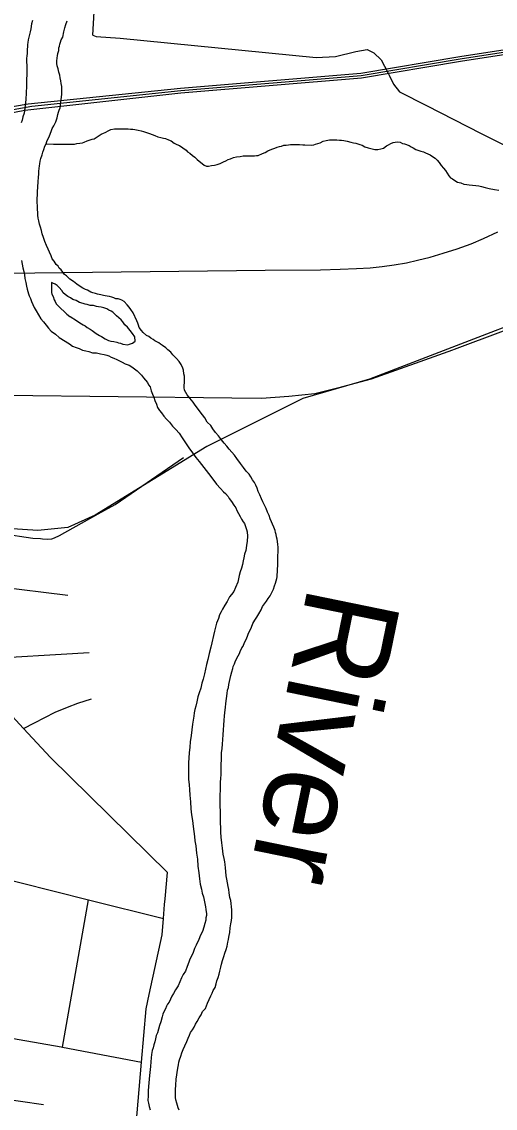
# Model space of a CAD drawing. Extents: x 0 to 44.3, y 0 to 22.
# Drawn here: x 5.125 to 5.6, y 17.715 to 18.805 of the extents above; entities that cross this region are included whole.
import ezdxf

# ---------------------------------------------------------------- set-up
doc = ezdxf.new("R2010")
doc.units = 0
for name, color, linetype in [('GM_X_City_Street', 7, 'Continuous'), ('GM_X_County_Road', 7, 'Continuous'), ('GM_X_Major_River', 7, 'Continuous'), ('GM_X_Major_River_Text', 7, 'Continuous'), ('GM_X_Minor_River', 7, 'Continuous'), ('GM_X_Rail_Line', 7, 'Continuous'), ('GM_X_State_Route', 7, 'Continuous'), ('GM_X_US_Route', 7, 'Continuous')]:
    doc.layers.add(name, color=color, linetype=linetype)

msp = doc.modelspace()

# ---------------------------------------------------------------- linework, layer by layer
at = {"layer": 'GM_X_City_Street'}
for p, q in [((5.0986, 18.2388), (5.1713, 18.2298)), ((5.1659, 17.7763), (5.192, 17.924)), ((5.092, 17.7266), (5.1469, 17.7186))]:
    msp.add_line(p, q, dxfattribs=at)
for points in [[(5.2016, 18.3113), (5.2187, 18.3209), (5.2872, 18.368)], [(5.105, 18.2915), (5.136, 18.287), (5.1437, 18.2866), (5.1459, 18.2864), (5.1504, 18.2859), (5.1551, 18.2863), (5.1578, 18.2873), (5.1628, 18.2896), (5.2016, 18.3113)], [(5.1078, 18.1672), (5.1644, 18.1705), (5.1927, 18.1721)], [(5.1266, 18.0961), (5.1376, 18.1017), (5.1583, 18.1124), (5.1709, 18.1175), (5.1813, 18.1215), (5.1948, 18.1258)], [(4.9677, 17.9802), (5.0685, 17.955), (5.1231, 17.9413), (5.192, 17.924), (5.2672, 17.9052)], [(5.0432, 17.7976), (5.1008, 17.7876), (5.1644, 17.7766), (5.1659, 17.7763), (5.2452, 17.7611)]]:
    msp.add_lwpolyline(points, dxfattribs=at)
at = {"layer": 'GM_X_County_Road'}
msp.add_line((5.5861, 18.6932), (5.7119, 18.6293), dxfattribs=at)
for points in [[(5.1962, 18.7916), (5.2074, 18.9861), (5.21, 19.0351), (5.2114, 19.0611), (5.2076, 19.0746), (5.2007, 19.0831)], [(5.1962, 18.7916), (5.1996, 18.7904), (5.2237, 18.7888), (5.4206, 18.7694), (5.44, 18.7703), (5.4603, 18.7755), (5.4717, 18.7774), (5.4783, 18.7741), (5.4859, 18.767), (5.4925, 18.7542), (5.4938, 18.7515)], [(5.4938, 18.7515), (5.4982, 18.7424), (5.5043, 18.7348), (5.5313, 18.7211), (5.5861, 18.6932)]]:
    msp.add_lwpolyline(points, dxfattribs=at)
at = {"layer": 'GM_X_Major_River'}
for points in [[(5.1358, 18.8064), (5.1347, 18.803), (5.134, 18.7981), (5.1333, 18.795), (5.1315, 18.787), (5.1311, 18.7843), (5.1308, 18.7824), (5.1308, 18.7798), (5.1304, 18.7779), (5.1305, 18.776), (5.1305, 18.7737), (5.1301, 18.7706), (5.1298, 18.7687), (5.1298, 18.7664), (5.1298, 18.7642), (5.1299, 18.7619), (5.1299, 18.7596), (5.1299, 18.7573)], [(5.1493, 18.6826), (5.1501, 18.6849), (5.1508, 18.6868), (5.1523, 18.6898), (5.1538, 18.6933), (5.1545, 18.6952), (5.1556, 18.6982), (5.1571, 18.7009), (5.159, 18.7047), (5.1604, 18.7089), (5.1612, 18.712), (5.1619, 18.7143), (5.1626, 18.7166), (5.1634, 18.7189), (5.1637, 18.7219), (5.1641, 18.7246), (5.1651, 18.7322), (5.1651, 18.7367), (5.165, 18.7402), (5.1646, 18.7432), (5.1642, 18.7459), (5.1634, 18.7489), (5.163, 18.7516), (5.1622, 18.7546), (5.1614, 18.758), (5.1606, 18.761), (5.1602, 18.7633), (5.1602, 18.7656), (5.1605, 18.769), (5.1609, 18.7709), (5.1612, 18.7732), (5.162, 18.7763), (5.1623, 18.7789), (5.1627, 18.7808), (5.163, 18.7827), (5.1638, 18.7847), (5.1645, 18.7869), (5.166, 18.7896), (5.1671, 18.795), (5.1682, 18.7992), (5.1693, 18.8026), (5.1704, 18.806)], [(5.1299, 18.7573), (5.1299, 18.755), (5.13, 18.7531), (5.13, 18.7508), (5.1296, 18.7486), (5.1296, 18.7467), (5.1297, 18.744), (5.1297, 18.7413), (5.1297, 18.7387), (5.1294, 18.736), (5.1294, 18.7337), (5.1294, 18.7314), (5.1291, 18.7295), (5.1291, 18.7269), (5.1288, 18.7246), (5.1284, 18.7216), (5.1281, 18.7185), (5.1274, 18.7136), (5.1259, 18.7097), (5.1252, 18.7063), (5.1244, 18.7036)], [(5.288, 18.4383), (5.288, 18.4406), (5.2883, 18.4428), (5.2883, 18.4447), (5.2883, 18.4466), (5.2882, 18.4497), (5.2878, 18.452), (5.2874, 18.4554), (5.2866, 18.4577), (5.2851, 18.4611), (5.2831, 18.4641), (5.2804, 18.4671), (5.2785, 18.469), (5.2766, 18.4709), (5.2747, 18.4735), (5.2716, 18.4761), (5.2697, 18.478), (5.2663, 18.4803), (5.2643, 18.4818), (5.2624, 18.4829), (5.2605, 18.484), (5.2586, 18.4851), (5.2567, 18.4863), (5.2544, 18.4878), (5.2525, 18.4893), (5.2502, 18.4904), (5.2468, 18.4934), (5.2452, 18.4953), (5.2429, 18.4983), (5.2421, 18.5006), (5.2413, 18.5028), (5.2405, 18.5051), (5.2367, 18.5131), (5.2343, 18.5165), (5.2328, 18.5187), (5.2309, 18.521), (5.2278, 18.5244), (5.2255, 18.5259), (5.2236, 18.5266), (5.2217, 18.527), (5.2194, 18.5273), (5.2175, 18.5281), (5.2152, 18.5288), (5.2129, 18.5296), (5.2107, 18.5299), (5.2088, 18.5303), (5.2069, 18.5306), (5.2042, 18.531), (5.2008, 18.5317), (5.1989, 18.5325), (5.1962, 18.5332), (5.1943, 18.5339), (5.1909, 18.5358), (5.1889, 18.5366), (5.1863, 18.538), (5.1836, 18.5395), (5.1802, 18.5418), (5.1767, 18.5444), (5.1733, 18.547), (5.1698, 18.5501), (5.1679, 18.5516), (5.166, 18.5538), (5.1644, 18.5561), (5.1625, 18.558), (5.1614, 18.5599), (5.1594, 18.5617), (5.1575, 18.5648), (5.1556, 18.5674), (5.1544, 18.5704), (5.1497, 18.5807), (5.1482, 18.5848), (5.1466, 18.5886), (5.1454, 18.5924), (5.1446, 18.5958), (5.1438, 18.5989), (5.1427, 18.6019), (5.1419, 18.6053), (5.1415, 18.608), (5.141, 18.611), (5.141, 18.6137), (5.1406, 18.6167), (5.1406, 18.6205), (5.1405, 18.6239), (5.1405, 18.6277), (5.1408, 18.6315), (5.1408, 18.635), (5.1411, 18.6391), (5.1414, 18.6449), (5.1418, 18.649), (5.1421, 18.6525), (5.1421, 18.6551), (5.1424, 18.6578), (5.1428, 18.6605), (5.1431, 18.6627), (5.1435, 18.6654), (5.1442, 18.6681), (5.1453, 18.6715), (5.146, 18.6742), (5.1471, 18.6769), (5.1482, 18.6803), (5.1493, 18.6826)], [(5.1245, 18.5656), (5.1253, 18.5618), (5.1261, 18.5584), (5.1269, 18.5546), (5.1277, 18.5512), (5.1281, 18.5474), (5.1289, 18.5436), (5.1297, 18.5398), (5.1305, 18.5367), (5.1309, 18.5345), (5.1317, 18.5322), (5.1325, 18.5303), (5.1336, 18.5276), (5.1348, 18.5246), (5.136, 18.5216), (5.1375, 18.5185), (5.1395, 18.5151), (5.1418, 18.511), (5.1441, 18.5072), (5.1468, 18.5042), (5.1495, 18.5008), (5.1518, 18.4978), (5.1545, 18.4948), (5.1587, 18.4918), (5.1625, 18.4884), (5.1729, 18.482), (5.1759, 18.4798), (5.1794, 18.4783), (5.1824, 18.4772), (5.1858, 18.4757), (5.1893, 18.4749), (5.1923, 18.4742), (5.1961, 18.4731), (5.1999, 18.4728), (5.2041, 18.472), (5.2075, 18.4713), (5.2102, 18.4706), (5.2125, 18.4698), (5.2148, 18.4687)], [(5.1547, 18.5434), (5.1548, 18.5336), (5.1552, 18.5317), (5.1564, 18.5294), (5.1576, 18.5263), (5.1583, 18.5245), (5.1595, 18.5222), (5.1618, 18.5199), (5.1641, 18.5173), (5.1676, 18.5143), (5.1703, 18.5116), (5.1733, 18.5094), (5.1736, 18.5093)], [(5.1736, 18.5093), (5.1798, 18.5053), (5.1821, 18.5038), (5.1848, 18.5019), (5.1867, 18.5012), (5.1886, 18.5), (5.1905, 18.4985), (5.1936, 18.4967), (5.1955, 18.4955), (5.1997, 18.4925), (5.2031, 18.4903), (5.205, 18.4892), (5.2085, 18.4869), (5.2119, 18.4854), (5.2142, 18.4847), (5.2172, 18.4843), (5.2203, 18.4836), (5.2222, 18.4829), (5.2241, 18.4825), (5.2264, 18.4818), (5.2313, 18.4811), (5.2332, 18.4815), (5.2362, 18.4826), (5.2389, 18.4846), (5.2384, 18.4891), (5.2361, 18.4925), (5.2338, 18.4952), (5.2311, 18.4986), (5.2284, 18.5012), (5.2265, 18.5042), (5.2246, 18.5061), (5.2223, 18.508), (5.22, 18.5102), (5.2165, 18.5136), (5.2146, 18.5147), (5.2123, 18.5159), (5.2104, 18.517), (5.2074, 18.5181), (5.2047, 18.5188), (5.2021, 18.5192), (5.1998, 18.5195), (5.1971, 18.5203), (5.1937, 18.5206), (5.1906, 18.5214), (5.1887, 18.5217), (5.1865, 18.5225), (5.183, 18.5236), (5.1796, 18.5254), (5.1762, 18.5265), (5.1739, 18.528), (5.1712, 18.5295), (5.1685, 18.5314), (5.1666, 18.5333), (5.165, 18.5356), (5.1624, 18.5386), (5.1604, 18.5405), (5.1585, 18.542), (5.1562, 18.5427), (5.1547, 18.5434)], [(5.2148, 18.4687), (5.2174, 18.4676), (5.2205, 18.4661), (5.2232, 18.465), (5.2258, 18.4635), (5.2289, 18.462), (5.2327, 18.4605), (5.2354, 18.459), (5.2381, 18.4568), (5.2407, 18.4549), (5.243, 18.4527), (5.2453, 18.4504), (5.2473, 18.4478), (5.2492, 18.4455), (5.2511, 18.4432), (5.2523, 18.441), (5.2538, 18.4387), (5.255, 18.4349), (5.2562, 18.4315), (5.2574, 18.4285), (5.2585, 18.425), (5.2601, 18.4216), (5.2613, 18.4182), (5.2632, 18.4152), (5.2651, 18.4126), (5.2674, 18.4095), (5.2701, 18.4065), (5.2732, 18.4035), (5.2763, 18.3994), (5.2797, 18.396), (5.2828, 18.3922), (5.2859, 18.3877), (5.2894, 18.3828), (5.2928, 18.3775), (5.2963, 18.3726), (5.2998, 18.368), (5.3032, 18.3639), (5.3148, 18.3488), (5.3206, 18.3412), (5.3244, 18.3367), (5.3275, 18.3333), (5.3294, 18.3318), (5.3321, 18.3288), (5.3333, 18.3269), (5.3356, 18.3239), (5.3379, 18.3201), (5.3398, 18.3175), (5.341, 18.3148), (5.3426, 18.3118), (5.3441, 18.3088), (5.3457, 18.3061), (5.3472, 18.3035), (5.3484, 18.3016), (5.3491, 18.2997), (5.3499, 18.2978), (5.3507, 18.2955), (5.3511, 18.2932), (5.3515, 18.2891), (5.3512, 18.2841), (5.3505, 18.2795), (5.3498, 18.2746), (5.3487, 18.2708), (5.348, 18.2673), (5.3473, 18.2643), (5.3465, 18.2605), (5.3455, 18.2567), (5.3443, 18.2532), (5.3433, 18.2494), (5.3418, 18.2429), (5.3396, 18.2376), (5.3377, 18.2334), (5.3355, 18.2303), (5.3336, 18.228), (5.3325, 18.2261), (5.331, 18.2234), (5.3288, 18.2196), (5.3266, 18.2158), (5.3251, 18.2131), (5.3236, 18.21), (5.3225, 18.2062), (5.3206, 18.2017), (5.3195, 18.1978), (5.3185, 18.1936), (5.3148, 18.1776), (5.313, 18.1711), (5.3116, 18.1651), (5.3105, 18.1601), (5.3094, 18.1555), (5.3083, 18.1509), (5.3072, 18.1456), (5.3058, 18.1414), (5.3047, 18.1365), (5.3032, 18.1319), (5.3017, 18.1277), (5.3007, 18.1227), (5.2996, 18.1185), (5.2988, 18.1151), (5.2981, 18.1117), (5.2978, 18.1082), (5.2971, 18.1044), (5.2964, 18.1002)], [(5.3299, 18.1211), (5.3313, 18.131), (5.3316, 18.1344), (5.3324, 18.1371), (5.3327, 18.1402), (5.3334, 18.1432), (5.3342, 18.1463), (5.3349, 18.1493), (5.336, 18.1527), (5.3367, 18.1562), (5.3371, 18.1581), (5.3386, 18.1608), (5.3393, 18.163), (5.3408, 18.1665), (5.3423, 18.1688), (5.3434, 18.1711), (5.3441, 18.1734), (5.346, 18.1768), (5.3471, 18.1787), (5.3486, 18.1822), (5.3501, 18.1852), (5.3515, 18.1886), (5.3526, 18.1917), (5.3541, 18.1948), (5.3556, 18.1978), (5.3571, 18.2013), (5.3589, 18.2047), (5.3608, 18.2078), (5.363, 18.2112), (5.3653, 18.215), (5.3668, 18.2185), (5.3686, 18.2211), (5.3705, 18.2238), (5.3724, 18.2265), (5.3742, 18.2292), (5.3757, 18.2319), (5.3776, 18.2357), (5.3787, 18.2391), (5.3798, 18.2418), (5.3805, 18.2441), (5.3809, 18.2464), (5.3812, 18.2483), (5.3812, 18.2506), (5.3816, 18.2528), (5.3822, 18.2627), (5.3822, 18.2658), (5.3821, 18.27), (5.3825, 18.2726), (5.3824, 18.2753), (5.3824, 18.278), (5.382, 18.2806), (5.3816, 18.2836), (5.3812, 18.2859), (5.3808, 18.2882), (5.3804, 18.2905), (5.3796, 18.2928), (5.3792, 18.2947), (5.378, 18.2981), (5.3768, 18.3011), (5.3757, 18.3034), (5.3745, 18.3064), (5.3733, 18.3098), (5.3718, 18.3132), (5.3702, 18.3166), (5.3687, 18.32), (5.3671, 18.3234), (5.3655, 18.3265), (5.364, 18.3303), (5.3624, 18.3337), (5.3612, 18.3371), (5.3601, 18.3401), (5.3585, 18.3427), (5.3566, 18.3454), (5.355, 18.3484), (5.3531, 18.3511), (5.3504, 18.3541), (5.3477, 18.3579), (5.3446, 18.362), (5.3408, 18.3669), (5.3385, 18.3703), (5.3358, 18.3733), (5.3331, 18.3763), (5.3308, 18.3794), (5.3281, 18.3824), (5.3254, 18.3858), (5.3223, 18.3896), (5.3196, 18.3929), (5.3169, 18.3967), (5.3146, 18.4001), (5.3112, 18.4035), (5.3088, 18.4077), (5.3065, 18.4107), (5.3, 18.419), (5.2984, 18.4216), (5.2969, 18.4235), (5.2953, 18.4254), (5.2938, 18.4273), (5.2911, 18.4307), (5.2896, 18.433), (5.2884, 18.4356), (5.288, 18.4383)], [(5.2799, 17.7441), (5.2816, 17.7551), (5.2824, 17.7586), (5.2827, 17.7612), (5.2834, 17.7635), (5.2845, 17.767), (5.2856, 17.7704), (5.2871, 17.7738), (5.2886, 17.7776), (5.2905, 17.7818), (5.2919, 17.7853), (5.2934, 17.7883), (5.2945, 17.791), (5.2964, 17.7937), (5.2979, 17.7964), (5.2994, 17.7994), (5.3012, 17.8021), (5.3031, 17.8056), (5.305, 17.8086), (5.3064, 17.8121), (5.3094, 17.8151), (5.3113, 17.8205), (5.3131, 17.8239), (5.3146, 17.8277), (5.3161, 17.8304), (5.3172, 17.8331), (5.3191, 17.8361), (5.3202, 17.8396), (5.3209, 17.8426), (5.322, 17.8461), (5.3231, 17.8495), (5.3238, 17.8525), (5.3249, 17.8564), (5.3256, 17.8594), (5.3264, 17.8632), (5.3278, 17.867), (5.3289, 17.8705), (5.33, 17.8743), (5.3311, 17.8777), (5.3318, 17.8815), (5.3326, 17.8842), (5.3329, 17.8865), (5.3333, 17.8884), (5.334, 17.8914), (5.3343, 17.896), (5.335, 17.8998), (5.3354, 17.9032), (5.3357, 17.9063), (5.3357, 17.9089), (5.3357, 17.9112), (5.3357, 17.9139), (5.3348, 17.9234), (5.334, 17.9264), (5.3332, 17.931), (5.3328, 17.9344), (5.3323, 17.9374), (5.3315, 17.9412), (5.3307, 17.9447), (5.3303, 17.9481), (5.3299, 17.9523), (5.3295, 17.956), (5.3291, 17.9595), (5.3287, 17.9621), (5.3282, 17.9655), (5.327, 17.9697), (5.3266, 17.9758), (5.3258, 17.9811), (5.3253, 17.9868), (5.3249, 17.9921), (5.3248, 17.9967), (5.3244, 18.0009), (5.3244, 18.0043), (5.3243, 18.0077), (5.3243, 18.0108), (5.3243, 18.0138), (5.3242, 18.0172), (5.3242, 18.0214), (5.3241, 18.0252), (5.3241, 18.0294), (5.3244, 18.034), (5.3244, 18.0381), (5.3243, 18.042), (5.3247, 18.0458), (5.325, 18.0499), (5.325, 18.0537), (5.3253, 18.0572), (5.3253, 18.061), (5.3256, 18.064), (5.3256, 18.0682), (5.3255, 18.0716), (5.3262, 18.0758), (5.3266, 18.0804), (5.3269, 18.085), (5.3272, 18.0895), (5.3275, 18.0945), (5.3279, 18.0994), (5.3282, 18.1044), (5.3285, 18.1082), (5.3289, 18.112), (5.3296, 18.1169), (5.3299, 18.1211)], [(5.2964, 18.1002), (5.2957, 18.0945), (5.295, 18.0888), (5.2939, 18.0827), (5.2936, 18.0774), (5.2929, 18.0717), (5.2926, 18.0664), (5.2922, 18.0614), (5.2923, 18.0572), (5.2923, 18.053), (5.2924, 18.0492), (5.2924, 18.0451), (5.2929, 18.0394), (5.2933, 18.0348), (5.2937, 18.0291), (5.2942, 18.0223), (5.2947, 18.0154), (5.2955, 18.0093), (5.2963, 18.0036), (5.2971, 17.9976), (5.2976, 17.9926), (5.2984, 17.9877), (5.2988, 17.9831), (5.2996, 17.9782), (5.3005, 17.971), (5.3013, 17.9649), (5.3018, 17.9577), (5.3026, 17.9512), (5.3034, 17.9451), (5.3042, 17.9398), (5.3054, 17.9349), (5.3062, 17.9307), (5.3074, 17.9269), (5.3094, 17.9171), (5.3098, 17.9144), (5.3102, 17.9121), (5.3103, 17.9102), (5.3103, 17.9083), (5.3099, 17.906), (5.3096, 17.9037), (5.3089, 17.9003), (5.3078, 17.8965), (5.3063, 17.8923), (5.3044, 17.8885), (5.3026, 17.8843), (5.3, 17.8785), (5.2985, 17.8751), (5.297, 17.8713), (5.2952, 17.8675), (5.2937, 17.8644), (5.2926, 17.8614), (5.2911, 17.8572), (5.2893, 17.8526), (5.287, 17.8491), (5.2852, 17.8457), (5.2837, 17.8419), (5.2819, 17.8377), (5.2792, 17.8338), (5.2774, 17.83), (5.2755, 17.8273), (5.2744, 17.8243), (5.2729, 17.8212), (5.2714, 17.8193), (5.2703, 17.8174), (5.2692, 17.8147), (5.2677, 17.8117), (5.2666, 17.8094), (5.2659, 17.8067), (5.2644, 17.8017), (5.2633, 17.7979), (5.2622, 17.7941), (5.2611, 17.7907), (5.26, 17.788), (5.2593, 17.7846), (5.2586, 17.7815), (5.2575, 17.7785), (5.2567, 17.7754), (5.256, 17.7728), (5.2553, 17.7689), (5.255, 17.7655), (5.2546, 17.7613), (5.2543, 17.7568), (5.2533, 17.7476), (5.2529, 17.7442), (5.2526, 17.7404), (5.2522, 17.7366), (5.2519, 17.7324), (5.252, 17.7275), (5.2516, 17.7225), (5.2521, 17.7199), (5.2528, 17.7168), (5.254, 17.7134)], [(5.2829, 17.7129), (5.2821, 17.7152), (5.2813, 17.7175), (5.2805, 17.7201), (5.2797, 17.7232), (5.2793, 17.7258), (5.2793, 17.7293), (5.2792, 17.7338), (5.2796, 17.738), (5.2799, 17.7441)]]:
    msp.add_lwpolyline(points, dxfattribs=at)
at = {"layer": 'GM_X_Minor_River'}
for points in [[(5.1494, 18.6828), (5.1569, 18.6823), (5.1592, 18.6823), (5.1611, 18.6823), (5.1634, 18.6823), (5.1657, 18.6824), (5.1695, 18.6824), (5.1714, 18.6824), (5.1736, 18.6824), (5.1755, 18.6825), (5.1778, 18.6825), (5.1801, 18.6829), (5.1831, 18.6833), (5.1858, 18.6837), (5.1877, 18.6845), (5.1907, 18.6857), (5.1926, 18.6864), (5.1956, 18.6872), (5.1975, 18.6876), (5.2047, 18.6923), (5.2069, 18.6934), (5.2088, 18.6942), (5.2122, 18.6961), (5.2145, 18.6969), (5.2179, 18.6977), (5.2205, 18.6977), (5.2228, 18.6978), (5.2251, 18.6978), (5.2277, 18.6978), (5.23, 18.6978), (5.2319, 18.6979), (5.2342, 18.6975), (5.2365, 18.6975), (5.2384, 18.6972), (5.2418, 18.6964), (5.2449, 18.6957), (5.2471, 18.695), (5.2502, 18.6942), (5.2532, 18.6931), (5.2559, 18.692), (5.2586, 18.6909), (5.2616, 18.6898), (5.2647, 18.6891), (5.2673, 18.6883), (5.2692, 18.688), (5.2723, 18.6868), (5.2749, 18.6857), (5.278, 18.6835), (5.2807, 18.682), (5.2834, 18.6809), (5.2868, 18.6786), (5.2899, 18.6764), (5.2914, 18.6745), (5.2937, 18.6734), (5.2964, 18.6711), (5.2987, 18.6692), (5.301, 18.667), (5.3079, 18.6613), (5.3105, 18.6602), (5.3124, 18.6602), (5.3155, 18.661), (5.3185, 18.6614), (5.3211, 18.6619), (5.3242, 18.663), (5.3276, 18.6646), (5.3298, 18.6657), (5.3321, 18.6669), (5.3344, 18.6677), (5.3374, 18.6689), (5.3404, 18.6697), (5.3442, 18.6701), (5.3472, 18.6705), (5.3491, 18.6705), (5.3518, 18.6705), (5.3548, 18.6706), (5.3586, 18.6706), (5.3605, 18.671), (5.3624, 18.671), (5.3666, 18.673), (5.3692, 18.6741), (5.3719, 18.6757), (5.3745, 18.6768), (5.3771, 18.6776), (5.379, 18.6784), (5.3813, 18.6792), (5.3836, 18.68), (5.3858, 18.6804), (5.3881, 18.6812), (5.3904, 18.6812), (5.3927, 18.6816), (5.3949, 18.682), (5.3984, 18.682), (5.4014, 18.682), (5.4037, 18.6821), (5.4071, 18.6817), (5.409, 18.6817), (5.4158, 18.6814), (5.4181, 18.6818)], [(5.4181, 18.6818), (5.42, 18.6822), (5.4223, 18.683), (5.4245, 18.6838), (5.4275, 18.6853), (5.4306, 18.6861), (5.434, 18.6866), (5.4363, 18.6866), (5.4389, 18.6866), (5.4412, 18.6866), (5.4439, 18.6863), (5.4461, 18.6863), (5.4484, 18.6859), (5.4515, 18.6852), (5.4553, 18.6845), (5.4579, 18.6838), (5.4602, 18.6834), (5.4625, 18.6827), (5.4644, 18.6819), (5.4667, 18.6812), (5.4694, 18.6797), (5.4728, 18.6786), (5.4766, 18.6775), (5.4796, 18.6771), (5.4823, 18.6771), (5.4853, 18.6776), (5.488, 18.6783), (5.491, 18.6807), (5.4932, 18.6818), (5.4955, 18.683), (5.4978, 18.6841), (5.4997, 18.6845), (5.5019, 18.6846), (5.505, 18.6842), (5.5073, 18.6831), (5.5092, 18.6827), (5.5138, 18.6809), (5.516, 18.6798), (5.518, 18.6786), (5.5206, 18.6771), (5.5225, 18.6764), (5.5256, 18.6753), (5.5282, 18.6746), (5.5302, 18.6738), (5.5328, 18.6727), (5.5351, 18.6716), (5.5374, 18.6701), (5.5401, 18.6682), (5.542, 18.6663), (5.5439, 18.6641), (5.5462, 18.661), (5.5485, 18.6584), (5.5505, 18.6558), (5.552, 18.6531), (5.5536, 18.6505), (5.5555, 18.6486), (5.5574, 18.6475), (5.5597, 18.646), (5.5624, 18.6441), (5.5658, 18.6434), (5.5688, 18.6423), (5.5719, 18.6419), (5.5742, 18.6416), (5.581, 18.6409), (5.5837, 18.6405), (5.5867, 18.6398), (5.5901, 18.639), (5.5943, 18.6379), (5.5997, 18.6369), (5.6038, 18.6361)]]:
    msp.add_lwpolyline(points, dxfattribs=at)
at = {"layer": 'GM_X_Rail_Line'}
for points in [[(4.2494, 18.2036), (4.3197, 18.2538), (4.3768, 18.2924), (4.4463, 18.3369), (4.5875, 18.4389), (4.6813, 18.502), (4.7573, 18.5537), (4.8159, 18.5951), (4.8399, 18.6112), (4.861, 18.6238), (4.8953, 18.6435), (4.919, 18.6554), (4.9429, 18.6669), (4.9712, 18.6779), (5.0065, 18.6914), (5.0411, 18.7025), (5.0781, 18.712), (5.1016, 18.7178), (5.1313, 18.7229), (5.2843, 18.7385), (5.4653, 18.7536), (5.5648, 18.7703), (5.6145, 18.778)], [(4.2507, 18.2017), (4.321, 18.2519), (4.3781, 18.2905), (4.448, 18.3351), (4.5888, 18.437), (4.7004, 18.5107), (4.7727, 18.5618), (4.8176, 18.5931), (4.8486, 18.6133), (4.8827, 18.6323), (4.9111, 18.6481), (4.9306, 18.6579), (4.9594, 18.6702), (4.9885, 18.6814), (5.0251, 18.694), (5.0593, 18.7031), (5.0934, 18.7132), (5.135, 18.7206), (5.2845, 18.7362), (5.4656, 18.7513), (5.5651, 18.768), (5.6149, 18.7757)], [(4.2521, 18.1998), (4.3224, 18.25), (4.3794, 18.2886), (4.4491, 18.3323), (4.5922, 18.4321), (4.7032, 18.5089), (4.7792, 18.5621), (4.8208, 18.5909), (4.8376, 18.6025), (4.858, 18.6147), (4.8838, 18.6296), (4.9116, 18.6439), (4.9476, 18.6601), (4.9744, 18.6722), (5.0073, 18.6846), (5.0594, 18.7003), (5.0944, 18.7101), (5.1281, 18.7166), (5.2847, 18.7339), (5.4659, 18.749), (5.5655, 18.7657), (5.6154, 18.7734)], [(5.1092, 18.553), (5.3692, 18.5558), (5.425, 18.5564), (5.4446, 18.5568), (5.4609, 18.5575), (5.4746, 18.5584), (5.4869, 18.5597), (5.4987, 18.5612), (5.5111, 18.5634), (5.5223, 18.5659), (5.5349, 18.5689), (5.5482, 18.5728), (5.5621, 18.5773), (5.576, 18.5824), (5.5884, 18.5876), (5.6031, 18.5945)], [(5.7335, 18.5462), (5.4742, 18.4465), (5.4073, 18.427), (5.3109, 18.379), (5.1987, 18.3102), (5.1713, 18.2976), (5.1411, 18.2948), (5.1054, 18.2969), (5.0969, 18.2445), (5.0591, 18.1618), (5.0399, 18.1234)]]:
    msp.add_lwpolyline(points, dxfattribs=at)
at = {"layer": 'GM_X_State_Route'}
for points in [[(5.2689, 17.9252), (5.2712, 17.9515), (5.1538, 18.0667), (5.1266, 18.0961), (5.1154, 18.1084)], [(5.2529, 17.8289), (5.2658, 17.8888), (5.2672, 17.9052), (5.2684, 17.9192), (5.2689, 17.9252)], [(5.2694, 17.3647), (5.2755, 17.3737), (5.2785, 17.4261), (5.2789, 17.4327), (5.2384, 17.6828), (5.2452, 17.7611), (5.2498, 17.8147), (5.2529, 17.8289)]]:
    msp.add_lwpolyline(points, dxfattribs=at)
at = {"layer": 'GM_X_US_Route'}
for p, q in [((5.5295, 18.4659), (5.5576, 18.476)), ((5.1077, 18.4304), (5.3358, 18.4279))]:
    msp.add_line(p, q, dxfattribs=at)
for points in [[(5.5576, 18.476), (5.5595, 18.4766), (5.7096, 18.5327), (5.7338, 18.5425), (5.7499, 18.5511), (5.8542, 18.6261), (5.884, 18.6488), (5.939, 18.685), (5.9879, 18.7167), (5.9956, 18.7216)], [(5.3358, 18.4279), (5.3655, 18.4275), (5.393, 18.4294), (5.4193, 18.432), (5.4461, 18.4387), (5.476, 18.4467), (5.5295, 18.4659)]]:
    msp.add_lwpolyline(points, dxfattribs=at)

# ---------------------------------------------------------------- texts
at = {"layer": 'GM_X_Major_River_Text'}
msp.add_text('River', height=0.09475, rotation=258.4205, dxfattribs=at).set_placement((5.413, 18.2414))

doc.saveas('drawing.dxf')
